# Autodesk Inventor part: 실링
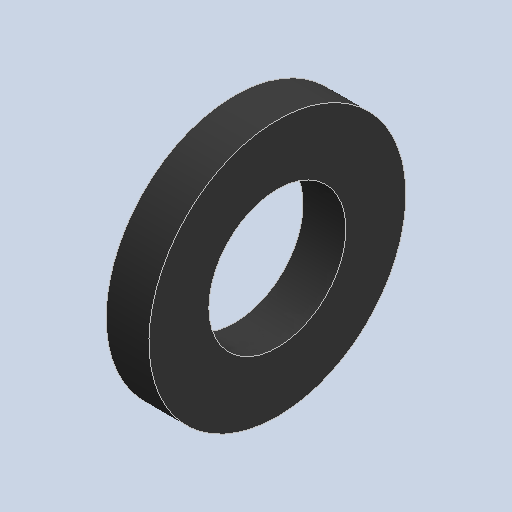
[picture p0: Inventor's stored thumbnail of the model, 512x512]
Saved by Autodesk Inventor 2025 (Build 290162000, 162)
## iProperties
Created: 2026-03
Part Number: 실링
Material: 고무, 실리콘
Document SubType Name: Modeling
Designer: KDI
Density: 1.25 g/cm^3
Appearance: 기본값
Author: jhkim
Sending System: Autodesk Inventor 2026
Preprocessor: ST-DEVELOPER v20.1
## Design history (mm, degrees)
feature "솔리드1"
node "솔리드2"
